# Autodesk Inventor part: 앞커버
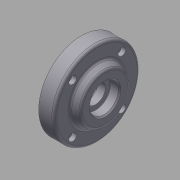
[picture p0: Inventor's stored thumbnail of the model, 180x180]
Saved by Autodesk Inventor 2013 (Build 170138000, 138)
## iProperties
Company: 한국ATC센터
Created: 2015-12
Part Number: 앞커버
Document SubType Name: Modeling
Designer: 앞커버
Density: 2.71 g/cm^3
Mass: 114.339 g
Surface Area: 117.889 cm^2
Volume: 42.1916 cm^3
Material: 알루미늄-6061
Author: mdu
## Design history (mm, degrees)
sketch "스케치1"
  geometry: L1 (-11.5, 0)-(11.5, 0); L2 (11.5, 0)-(11.5, 22.5); L3 (11.5, 22.5)-(6.5, 22.5); L4 (6.5, 22.5)-(6.5, 32.5); L5 (6.5, 32.5)-(-5.5, 32.5); L6 (-5.5, 32.5)-(-5.5, 21); L7 (-5.5, 21)-(-11.5, 18.202); L8 (-11.5, 18.202)-(-11.5, 0); 2 further points
  constraints: 16 end point, 3 parallel, 3 perpendicular, 1 coincident, 1 horizontal, 1 midpoint
  dimensions: "d0" = 23 distance of L1.start L1.end; "d1" = 65 diameter of L5 L1; "d2" = 45 diameter of L3 L1; "d3" = 42 diameter of L6.end L1; "d4" = 115 deg angle of L7 L6; "d5" = 12 distance of L4.end L5.end; "d6" = 5 distance of L2.end L3.end
revolve "회전1" sketch "스케치1" stored, may be unused: angle "d7" = 90 deg
sketch "스케치2"
  geometry: L1 (0, 0)-(32.5, 0); L2 (0, 0)-(18.738, 18.738); 1 further point
  constraints: 4 end point, 1 horizontal, 1 horizontal alignment, 1 other
  dimensions: "d8" = 45 deg angle of L1 L2; "d9" = 26.5 distance of L1.start L2.end
hole "구멍1" sketch "스케치2" at (18.738, 18.738) diameter "d10" = 3.4; stored, may be unused: countersink angle "d14" = 90 deg, drill point angle "d16" = 118 deg; dims "d11" = 6, "d12" = 6, "d13" = 3.3, "d15" = 8
fillet "모깎기1" dims "d20" = 2
hole "구멍2" diameter "d23" = 15; stored, may be unused: countersink angle "d27" = 90 deg, drill point angle "d29" = 118 deg; dims "d21" = 10, "d22" = 10, "d24" = 6, "d25" = 32, "d26" = 10, "d28" = 8
hole "구멍3" diameter "d32" = 22; stored, may be unused: countersink angle "d36" = 90 deg, drill point angle "d38" = 0 deg; dims "d30" = 10, "d31" = 10, "d33" = 6, "d34" = 32, "d35" = 10, "d37" = 7.3
chamfer "모따기1" distance "d39" = 1; stored, may be unused: second distance "d40" = 2, angle "d41" = 45 deg
fillet "모깎기2" dims "d42" = 0.3
node "솔리드1"
pattern_circular "원형 패턴1" dims angle "d18" = 360 deg
